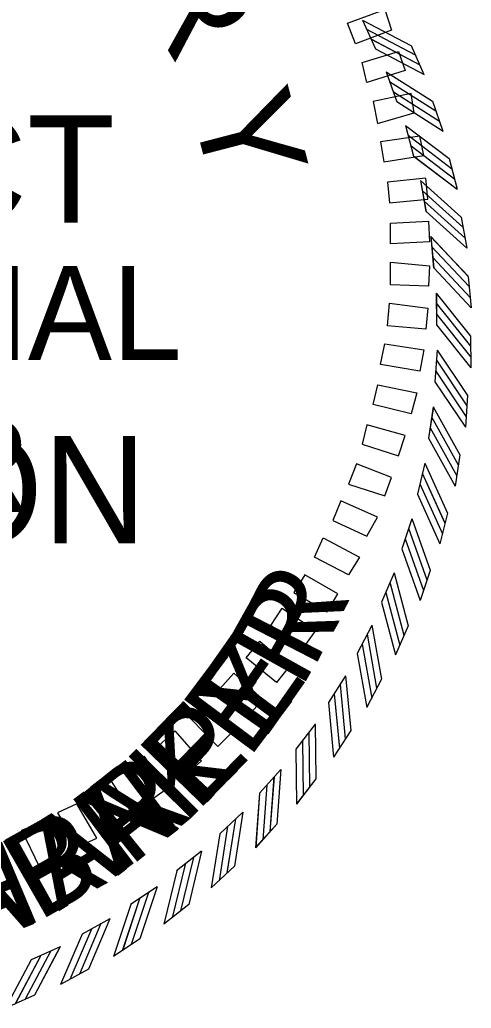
# Model space of a CAD drawing. Extents: x 16 to 1228740, y 11 to 152440.
# Drawn here: x 17.7977 to 17.8514, y 10.8205 to 10.9382 of the extents above; entities that cross this region are included whole.
import ezdxf

# ---------------------------------------------------------------- set-up
doc = ezdxf.new("R2010")
doc.units = 0
for name, color, linetype in [('B_StampERBB', 7, 'Continuous'), ('STAMP_FRED', 7, 'Continuous'), ('STAMP_JUSTIN', 7, 'Continuous'), ('STAMP_PRELIM', 7, 'Continuous')]:
    doc.layers.add(name, color=color, linetype=linetype)

msp = doc.modelspace()

# ---------------------------------------------------------------- linework, layer by layer
at = {"layer": 'B_StampERBB'}
for p, q in [((17.8385, 10.93817), (17.84005, 10.93472)), ((17.84427, 10.93512), (17.84581, 10.93169)), ((17.84132, 10.932), (17.84258, 10.92844)), ((17.84682, 10.92849), (17.84807, 10.92494)), ((17.84362, 10.92562), (17.84458, 10.92197)), ((17.84881, 10.92167), (17.84977, 10.91802)), ((17.84539, 10.91908), (17.84605, 10.91535)), ((17.85023, 10.91471), (17.85089, 10.91099)), ((17.84661, 10.9124), (17.84696, 10.90864)), ((17.85108, 10.90765), (17.85142, 10.9039)), ((17.84728, 10.90566), (17.84731, 10.90188)), ((17.85133, 10.90055), (17.85137, 10.89678)), ((17.84738, 10.89887), (17.8471, 10.89511)), ((17.851, 10.89345), (17.85073, 10.88969)), ((17.84693, 10.89211), (17.84634, 10.88837)), ((17.85009, 10.8864), (17.8495, 10.88268)), ((17.84591, 10.8854), (17.84502, 10.88173)), ((17.8486, 10.87945), (17.8477, 10.87579)), ((17.84435, 10.8788), (17.84316, 10.87522)), ((17.84225, 10.87235), (17.84076, 10.86888)), ((17.84653, 10.87265), (17.84534, 10.86908)), ((17.83962, 10.8661), (17.83786, 10.86276)), ((17.84392, 10.86605), (17.84243, 10.86258)), ((17.83649, 10.86009), (17.83445, 10.85691)), ((17.84076, 10.85968), (17.839, 10.85635)), ((17.83287, 10.85435), (17.83058, 10.85135)), ((17.83709, 10.85359), (17.83506, 10.85042)), ((17.82879, 10.84894), (17.82625, 10.84613)), ((17.83293, 10.84783), (17.83065, 10.84483)), ((17.82427, 10.84388), (17.82152, 10.84129)), ((17.82831, 10.84243), (17.82579, 10.83963)), ((17.81935, 10.83921), (17.81639, 10.83686)), ((17.82326, 10.83743), (17.82051, 10.83485)), ((17.81407, 10.83496), (17.81092, 10.83286)), ((17.81782, 10.83287), (17.81486, 10.83052)), ((17.80845, 10.83116), (17.80514, 10.82933)), ((17.81201, 10.82877), (17.80888, 10.82667)), ((17.80254, 10.82784), (17.79909, 10.82629)), ((17.80589, 10.82516), (17.80259, 10.82333)), ((17.79949, 10.82207), (17.79605, 10.82052))]:
    msp.add_line(p, q, dxfattribs=at)
for points in [[(17.83849, 10.93817), (17.84426, 10.93513)], [(17.83898, 10.93706), (17.84475, 10.93402)], [(17.83955, 10.93588), (17.84531, 10.93283)], [(17.84005, 10.93473), (17.84582, 10.93168)], [(17.84132, 10.93201), (17.84681, 10.92849)], [(17.84171, 10.93086), (17.84721, 10.92735)], [(17.84217, 10.92963), (17.84767, 10.92612)], [(17.84258, 10.92845), (17.84808, 10.92493)], [(17.84362, 10.92563), (17.84881, 10.92167)], [(17.84392, 10.92445), (17.8491, 10.9205)], [(17.84428, 10.92319), (17.84947, 10.91924)], [(17.84459, 10.92197), (17.84977, 10.91802)], [(17.84539, 10.91908), (17.85023, 10.91471)], [(17.84558, 10.91788), (17.85043, 10.91351)], [(17.84584, 10.9166), (17.85068, 10.91223)], [(17.84605, 10.91536), (17.85089, 10.91099)], [(17.84661, 10.91241), (17.85107, 10.90765)], [(17.84671, 10.9112), (17.85117, 10.90645)], [(17.84686, 10.9099), (17.85132, 10.90514)], [(17.84696, 10.90865), (17.85143, 10.90389)], [(17.84727, 10.90566), (17.85133, 10.90055)], [(17.84727, 10.90445), (17.85133, 10.89934)], [(17.84731, 10.90314), (17.85137, 10.89803)], [(17.84731, 10.90188), (17.85137, 10.89677)], [(17.84738, 10.89888), (17.851, 10.89345)], [(17.84728, 10.89767), (17.8509, 10.89225)], [(17.84721, 10.89636), (17.85083, 10.89094)], [(17.84711, 10.89511), (17.85073, 10.88969)], [(17.84692, 10.89211), (17.85009, 10.88641)], [(17.84672, 10.89092), (17.84989, 10.88521)], [(17.84655, 10.88962), (17.84971, 10.88391)], [(17.84634, 10.88838), (17.84951, 10.88267)], [(17.84591, 10.88541), (17.84859, 10.87946)], [(17.84561, 10.88423), (17.8483, 10.87828)], [(17.84533, 10.88295), (17.84801, 10.877)], [(17.84502, 10.88173), (17.84771, 10.87579)], [(17.84435, 10.87881), (17.84653, 10.87266)], [(17.84396, 10.87766), (17.84614, 10.87151)], [(17.84357, 10.87641), (17.84575, 10.87026)], [(17.84316, 10.87522), (17.84534, 10.86907)], [(17.84225, 10.87236), (17.84391, 10.86605)], [(17.84176, 10.87125), (17.84343, 10.86494)], [(17.84127, 10.87003), (17.84294, 10.86373)], [(17.84077, 10.86888), (17.84243, 10.86258)], [(17.83962, 10.86611), (17.84076, 10.85968)], [(17.83904, 10.86504), (17.84018, 10.85862)], [(17.83846, 10.86387), (17.8396, 10.85745)], [(17.83786, 10.86276), (17.839, 10.85634)], [(17.83649, 10.86009), (17.83709, 10.8536)], [(17.83582, 10.85908), (17.83643, 10.85258)], [(17.83514, 10.85796), (17.83575, 10.85146)], [(17.83446, 10.85691), (17.83506, 10.85041)], [(17.83287, 10.85436), (17.83293, 10.84784)], [(17.83135, 10.85234), (17.83142, 10.84582)], [(17.83212, 10.8534), (17.83219, 10.84688)], [(17.83058, 10.85135), (17.83065, 10.84483)], [(17.82879, 10.84894), (17.82831, 10.84244)], [(17.82797, 10.84805), (17.82749, 10.84154)], [(17.82711, 10.84706), (17.82664, 10.84055)], [(17.82626, 10.84613), (17.82579, 10.83963)], [(17.82338, 10.84306), (17.82237, 10.83661)], [(17.82427, 10.84388), (17.82326, 10.83744)], [(17.82244, 10.84214), (17.82144, 10.8357)], [(17.82152, 10.84129), (17.82051, 10.83485)], [(17.8184, 10.83847), (17.81686, 10.83213)], [(17.81936, 10.83921), (17.81782, 10.83287)], [(17.81739, 10.83763), (17.81585, 10.83129)], [(17.8164, 10.83686), (17.81486, 10.83052)], [(17.81407, 10.83496), (17.81202, 10.82877)], [(17.81198, 10.83355), (17.80993, 10.82736)], [(17.81305, 10.8343), (17.811, 10.82811)], [(17.81093, 10.83286), (17.80887, 10.82667)], [(17.80845, 10.83116), (17.80589, 10.82516)], [(17.80625, 10.82993), (17.80369, 10.82393)], [(17.80738, 10.83059), (17.80483, 10.82459)], [(17.80515, 10.82933), (17.80259, 10.82333)], [(17.80254, 10.82784), (17.79949, 10.82208)], [(17.80024, 10.82679), (17.7972, 10.82102)], [(17.80143, 10.82736), (17.79838, 10.82159)], [(17.79909, 10.82629), (17.79605, 10.82052)]]:
    msp.add_lwpolyline(points, dxfattribs=at)
at = {"layer": 'STAMP_FRED'}
for p, q in [((17.8385, 10.93817), (17.84005, 10.93472)), ((17.84427, 10.93512), (17.84581, 10.93169)), ((17.84132, 10.932), (17.84258, 10.92844)), ((17.84682, 10.92849), (17.84807, 10.92494)), ((17.84362, 10.92562), (17.84458, 10.92197)), ((17.84881, 10.92167), (17.84977, 10.91802)), ((17.84539, 10.91908), (17.84605, 10.91535)), ((17.85023, 10.91471), (17.85089, 10.91099)), ((17.84661, 10.9124), (17.84696, 10.90864)), ((17.85108, 10.90765), (17.85142, 10.9039)), ((17.84728, 10.90566), (17.84731, 10.90188)), ((17.85133, 10.90055), (17.85137, 10.89678)), ((17.84738, 10.89887), (17.8471, 10.89511)), ((17.851, 10.89345), (17.85073, 10.88969)), ((17.84693, 10.89211), (17.84634, 10.88837)), ((17.85009, 10.8864), (17.8495, 10.88268)), ((17.84591, 10.8854), (17.84502, 10.88173)), ((17.8486, 10.87945), (17.8477, 10.87579)), ((17.84435, 10.8788), (17.84316, 10.87522)), ((17.84225, 10.87235), (17.84076, 10.86888)), ((17.84653, 10.87265), (17.84534, 10.86908)), ((17.83962, 10.8661), (17.83786, 10.86276)), ((17.84392, 10.86605), (17.84243, 10.86258)), ((17.83649, 10.86009), (17.83445, 10.85691)), ((17.84076, 10.85968), (17.839, 10.85635)), ((17.83287, 10.85435), (17.83058, 10.85135)), ((17.83709, 10.85359), (17.83506, 10.85042)), ((17.82879, 10.84894), (17.82625, 10.84613)), ((17.83293, 10.84783), (17.83065, 10.84483)), ((17.82427, 10.84388), (17.82152, 10.84129)), ((17.82831, 10.84243), (17.82579, 10.83963)), ((17.81935, 10.83921), (17.81639, 10.83686)), ((17.82326, 10.83743), (17.82051, 10.83485)), ((17.81407, 10.83496), (17.81092, 10.83286)), ((17.81782, 10.83287), (17.81486, 10.83052)), ((17.80845, 10.83116), (17.80514, 10.82933)), ((17.81201, 10.82877), (17.80888, 10.82667)), ((17.80254, 10.82784), (17.79909, 10.82629)), ((17.80589, 10.82516), (17.80259, 10.82333)), ((17.79949, 10.82207), (17.79605, 10.82052))]:
    msp.add_line(p, q, dxfattribs=at)
for points in [[(17.83849, 10.93817), (17.84426, 10.93513)], [(17.83898, 10.93706), (17.84475, 10.93402)], [(17.83955, 10.93588), (17.84531, 10.93283)], [(17.84005, 10.93473), (17.84582, 10.93168)], [(17.84132, 10.93201), (17.84681, 10.92849)], [(17.84171, 10.93086), (17.84721, 10.92735)], [(17.84217, 10.92963), (17.84767, 10.92612)], [(17.84258, 10.92845), (17.84808, 10.92493)], [(17.84362, 10.92563), (17.84881, 10.92167)], [(17.84392, 10.92445), (17.8491, 10.9205)], [(17.84428, 10.92319), (17.84947, 10.91924)], [(17.84459, 10.92197), (17.84977, 10.91802)], [(17.84539, 10.91908), (17.85023, 10.91471)], [(17.84558, 10.91788), (17.85043, 10.91351)], [(17.84584, 10.9166), (17.85068, 10.91223)], [(17.84605, 10.91536), (17.85089, 10.91099)], [(17.84661, 10.91241), (17.85107, 10.90765)], [(17.84671, 10.9112), (17.85117, 10.90645)], [(17.84686, 10.9099), (17.85132, 10.90514)], [(17.84696, 10.90865), (17.85143, 10.90389)], [(17.84727, 10.90566), (17.85133, 10.90055)], [(17.84727, 10.90445), (17.85133, 10.89934)], [(17.84731, 10.90314), (17.85137, 10.89803)], [(17.84731, 10.90188), (17.85137, 10.89677)], [(17.84738, 10.89888), (17.851, 10.89345)], [(17.84728, 10.89767), (17.8509, 10.89225)], [(17.84721, 10.89636), (17.85083, 10.89094)], [(17.84711, 10.89511), (17.85073, 10.88969)], [(17.84692, 10.89211), (17.85009, 10.88641)], [(17.84672, 10.89092), (17.84989, 10.88521)], [(17.84655, 10.88962), (17.84971, 10.88391)], [(17.84634, 10.88838), (17.84951, 10.88267)], [(17.84591, 10.88541), (17.84859, 10.87946)], [(17.84561, 10.88423), (17.8483, 10.87828)], [(17.84533, 10.88295), (17.84801, 10.877)], [(17.84502, 10.88173), (17.84771, 10.87579)], [(17.84435, 10.87881), (17.84653, 10.87266)], [(17.84396, 10.87766), (17.84614, 10.87151)], [(17.84357, 10.87641), (17.84575, 10.87026)], [(17.84316, 10.87522), (17.84534, 10.86907)], [(17.84225, 10.87236), (17.84391, 10.86605)], [(17.84176, 10.87125), (17.84343, 10.86494)], [(17.84127, 10.87003), (17.84294, 10.86373)], [(17.84077, 10.86888), (17.84243, 10.86258)], [(17.83962, 10.86611), (17.84076, 10.85968)], [(17.83904, 10.86504), (17.84018, 10.85862)], [(17.83846, 10.86387), (17.8396, 10.85745)], [(17.83786, 10.86276), (17.839, 10.85634)], [(17.83649, 10.86009), (17.83709, 10.8536)], [(17.83582, 10.85908), (17.83643, 10.85258)], [(17.83514, 10.85796), (17.83575, 10.85146)], [(17.83446, 10.85691), (17.83506, 10.85041)], [(17.83287, 10.85436), (17.83293, 10.84784)], [(17.83135, 10.85234), (17.83142, 10.84582)], [(17.83212, 10.8534), (17.83219, 10.84688)], [(17.83058, 10.85135), (17.83065, 10.84483)], [(17.82879, 10.84894), (17.82831, 10.84244)], [(17.82797, 10.84805), (17.82749, 10.84154)], [(17.82711, 10.84706), (17.82664, 10.84055)], [(17.82626, 10.84613), (17.82579, 10.83963)], [(17.82338, 10.84306), (17.82237, 10.83661)], [(17.82427, 10.84388), (17.82326, 10.83744)], [(17.82244, 10.84214), (17.82144, 10.8357)], [(17.82152, 10.84129), (17.82051, 10.83485)], [(17.8184, 10.83847), (17.81686, 10.83213)], [(17.81936, 10.83921), (17.81782, 10.83287)], [(17.81739, 10.83763), (17.81585, 10.83129)], [(17.8164, 10.83686), (17.81486, 10.83052)], [(17.81407, 10.83496), (17.81202, 10.82877)], [(17.81198, 10.83355), (17.80993, 10.82736)], [(17.81305, 10.8343), (17.811, 10.82811)], [(17.81093, 10.83286), (17.80887, 10.82667)], [(17.80845, 10.83116), (17.80589, 10.82516)], [(17.80625, 10.82993), (17.80369, 10.82393)], [(17.80738, 10.83059), (17.80483, 10.82459)], [(17.80515, 10.82933), (17.80259, 10.82333)], [(17.80254, 10.82784), (17.79949, 10.82208)], [(17.80024, 10.82679), (17.7972, 10.82102)], [(17.80143, 10.82736), (17.79838, 10.82159)], [(17.79909, 10.82629), (17.79605, 10.82052)]]:
    msp.add_lwpolyline(points, dxfattribs=at)
at = {"layer": 'STAMP_JUSTIN'}
for p, q in [((17.8385, 10.93817), (17.84005, 10.93472)), ((17.84427, 10.93512), (17.84581, 10.93169)), ((17.84132, 10.932), (17.84258, 10.92844)), ((17.84682, 10.92849), (17.84807, 10.92494)), ((17.84362, 10.92562), (17.84458, 10.92197)), ((17.84881, 10.92167), (17.84977, 10.91802)), ((17.84539, 10.91908), (17.84604, 10.91536)), ((17.85023, 10.91471), (17.85089, 10.91099)), ((17.84661, 10.91241), (17.84695, 10.90864)), ((17.85107, 10.90765), (17.85142, 10.9039)), ((17.84727, 10.90566), (17.84731, 10.90188)), ((17.85133, 10.90055), (17.85137, 10.89678)), ((17.84738, 10.89888), (17.8471, 10.89511)), ((17.851, 10.89345), (17.85073, 10.88969)), ((17.84692, 10.89211), (17.84634, 10.88838)), ((17.85009, 10.8864), (17.8495, 10.88268)), ((17.84591, 10.8854), (17.84502, 10.88173)), ((17.84859, 10.87946), (17.8477, 10.87579)), ((17.84435, 10.8788), (17.84316, 10.87522)), ((17.84225, 10.87236), (17.84076, 10.86888)), ((17.84653, 10.87265), (17.84534, 10.86908)), ((17.83962, 10.8661), (17.83785, 10.86276)), ((17.84391, 10.86605), (17.84243, 10.86258)), ((17.83649, 10.86009), (17.83445, 10.85691)), ((17.84076, 10.85968), (17.839, 10.85635)), ((17.83287, 10.85435), (17.83057, 10.85135)), ((17.83709, 10.85359), (17.83506, 10.85042)), ((17.82879, 10.84894), (17.82625, 10.84614)), ((17.83293, 10.84783), (17.83064, 10.84484)), ((17.82427, 10.84388), (17.82151, 10.84129)), ((17.82831, 10.84243), (17.82578, 10.83964)), ((17.81935, 10.83921), (17.81639, 10.83686)), ((17.82326, 10.83743), (17.82051, 10.83485)), ((17.81407, 10.83496), (17.81092, 10.83286)), ((17.81782, 10.83287), (17.81486, 10.83053)), ((17.80845, 10.83116), (17.80514, 10.82933)), ((17.81201, 10.82877), (17.80887, 10.82668)), ((17.80253, 10.82784), (17.79909, 10.82629)), ((17.80589, 10.82516), (17.80259, 10.82334)), ((17.79949, 10.82207), (17.79605, 10.82053))]:
    msp.add_line(p, q, dxfattribs=at)
for points in [[(17.83849, 10.93817), (17.84426, 10.93513)], [(17.83898, 10.93706), (17.84475, 10.93402)], [(17.83954, 10.93588), (17.84531, 10.93283)], [(17.84005, 10.93473), (17.84582, 10.93168)], [(17.84131, 10.93201), (17.84681, 10.92849)], [(17.84171, 10.93086), (17.8472, 10.92735)], [(17.84217, 10.92963), (17.84767, 10.92612)], [(17.84258, 10.92845), (17.84808, 10.92493)], [(17.84362, 10.92563), (17.8488, 10.92167)], [(17.84391, 10.92445), (17.8491, 10.9205)], [(17.84427, 10.92319), (17.84946, 10.91924)], [(17.84458, 10.92197), (17.84977, 10.91802)], [(17.84538, 10.91908), (17.85023, 10.91471)], [(17.84558, 10.91788), (17.85043, 10.91351)], [(17.84584, 10.9166), (17.85068, 10.91223)], [(17.84605, 10.91536), (17.85089, 10.91099)], [(17.8466, 10.91241), (17.85107, 10.90766)], [(17.8467, 10.9112), (17.85117, 10.90645)], [(17.84685, 10.9099), (17.85132, 10.90515)], [(17.84696, 10.90865), (17.85142, 10.90389)], [(17.84727, 10.90566), (17.85133, 10.90055)], [(17.84727, 10.90445), (17.85133, 10.89934)], [(17.84731, 10.90314), (17.85137, 10.89803)], [(17.84731, 10.90188), (17.85137, 10.89678)], [(17.84738, 10.89888), (17.851, 10.89346)], [(17.84728, 10.89767), (17.8509, 10.89225)], [(17.84721, 10.89636), (17.85083, 10.89094)], [(17.8471, 10.89511), (17.85073, 10.88969)], [(17.84692, 10.89211), (17.85008, 10.88641)], [(17.84672, 10.89092), (17.84988, 10.88521)], [(17.84655, 10.88962), (17.84971, 10.88391)], [(17.84634, 10.88838), (17.8495, 10.88268)], [(17.84591, 10.88541), (17.84859, 10.87946)], [(17.84561, 10.88423), (17.84829, 10.87829)], [(17.84533, 10.88295), (17.84801, 10.87701)], [(17.84502, 10.88174), (17.8477, 10.87579)], [(17.84435, 10.87881), (17.84653, 10.87266)], [(17.84395, 10.87766), (17.84614, 10.87151)], [(17.84357, 10.87641), (17.84575, 10.87026)], [(17.84316, 10.87522), (17.84534, 10.86907)], [(17.84225, 10.87236), (17.84391, 10.86605)], [(17.84176, 10.87125), (17.84343, 10.86494)], [(17.84127, 10.87003), (17.84294, 10.86373)], [(17.84077, 10.86888), (17.84243, 10.86258)], [(17.83962, 10.86611), (17.84076, 10.85969)], [(17.83904, 10.86504), (17.84018, 10.85862)], [(17.83846, 10.86387), (17.8396, 10.85745)], [(17.83786, 10.86277), (17.839, 10.85634)], [(17.83649, 10.8601), (17.83709, 10.8536)], [(17.83582, 10.85908), (17.83643, 10.85258)], [(17.83514, 10.85796), (17.83575, 10.85147)], [(17.83445, 10.85691), (17.83506, 10.85041)], [(17.83287, 10.85436), (17.83293, 10.84784)], [(17.83135, 10.85234), (17.83142, 10.84582)], [(17.83212, 10.8534), (17.83219, 10.84688)], [(17.83058, 10.85135), (17.83064, 10.84483)], [(17.82879, 10.84894), (17.82831, 10.84244)], [(17.82796, 10.84805), (17.82749, 10.84155)], [(17.82711, 10.84706), (17.82663, 10.84055)], [(17.82626, 10.84614), (17.82578, 10.83963)], [(17.82338, 10.84306), (17.82237, 10.83662)], [(17.82427, 10.84388), (17.82326, 10.83744)], [(17.82244, 10.84215), (17.82144, 10.8357)], [(17.82152, 10.84129), (17.82051, 10.83485)], [(17.8184, 10.83847), (17.81686, 10.83213)], [(17.81935, 10.83921), (17.81782, 10.83287)], [(17.81739, 10.83763), (17.81585, 10.83129)], [(17.8164, 10.83686), (17.81486, 10.83052)], [(17.81407, 10.83496), (17.81201, 10.82877)], [(17.81198, 10.83355), (17.80992, 10.82736)], [(17.81305, 10.8343), (17.811, 10.82811)], [(17.81093, 10.83286), (17.80887, 10.82667)], [(17.80845, 10.83117), (17.80589, 10.82517)], [(17.80625, 10.82993), (17.80369, 10.82393)], [(17.80738, 10.83059), (17.80482, 10.82459)], [(17.80515, 10.82933), (17.80259, 10.82333)], [(17.80254, 10.82785), (17.79949, 10.82208)], [(17.80024, 10.8268), (17.7972, 10.82103)], [(17.80143, 10.82736), (17.79838, 10.82159)], [(17.79909, 10.82629), (17.79605, 10.82052)]]:
    msp.add_lwpolyline(points, dxfattribs=at)
at = {"layer": 'STAMP_PRELIM'}
for p, q in [((17.83671, 10.93778), (17.84115, 10.93941)), ((17.84115, 10.93941), (17.84196, 10.93697)), ((17.83765, 10.93535), (17.83671, 10.93778)), ((17.84196, 10.93697), (17.83765, 10.93535)), ((17.83846, 10.9331), (17.84278, 10.93441)), ((17.84278, 10.93441), (17.84358, 10.93216)), ((17.83903, 10.93072), (17.83846, 10.9331)), ((17.84358, 10.93216), (17.83903, 10.93072)), ((17.84428, 10.92941), (17.83978, 10.92847)), ((17.84465, 10.9271), (17.84428, 10.92941)), ((17.83978, 10.92847), (17.84028, 10.92585)), ((17.84028, 10.92585), (17.84465, 10.9271)), ((17.84533, 10.92435), (17.84065, 10.92366)), ((17.84578, 10.92203), (17.84533, 10.92435)), ((17.84065, 10.92366), (17.84103, 10.92128)), ((17.84103, 10.92128), (17.84578, 10.92203)), ((17.84603, 10.91935), (17.84146, 10.91885)), ((17.84628, 10.91685), (17.84603, 10.91935)), ((17.84146, 10.91885), (17.84171, 10.91641)), ((17.84171, 10.91641), (17.84628, 10.91685)), ((17.84183, 10.91397), (17.84633, 10.91422)), ((17.84183, 10.91153), (17.84183, 10.91397)), ((17.84633, 10.91422), (17.84646, 10.91178)), ((17.84646, 10.91178), (17.84183, 10.91153)), ((17.84183, 10.90935), (17.84646, 10.90891)), ((17.84183, 10.90666), (17.84183, 10.90935)), ((17.84646, 10.90891), (17.84633, 10.90647)), ((17.84633, 10.90647), (17.84183, 10.90666)), ((17.84146, 10.90178), (17.84171, 10.90447)), ((17.84171, 10.90447), (17.84628, 10.90385)), ((17.84628, 10.90385), (17.84603, 10.90135)), ((17.84603, 10.90135), (17.84146, 10.90178)), ((17.84065, 10.89716), (17.84115, 10.8996)), ((17.84115, 10.8996), (17.84578, 10.89891)), ((17.84578, 10.89891), (17.84533, 10.89635)), ((17.84533, 10.89635), (17.84065, 10.89716)), ((17.83978, 10.89241), (17.84033, 10.89472)), ((17.84033, 10.89472), (17.84496, 10.89378)), ((17.84496, 10.89378), (17.84428, 10.89128)), ((17.84428, 10.89128), (17.83978, 10.89241)), ((17.83903, 10.88997), (17.83846, 10.88766)), ((17.84358, 10.88872), (17.83903, 10.88997)), ((17.84278, 10.88628), (17.84358, 10.88872)), ((17.83846, 10.88766), (17.84278, 10.88628)), ((17.83778, 10.88535), (17.83683, 10.88291)), ((17.84196, 10.88372), (17.83778, 10.88535)), ((17.83683, 10.88291), (17.84115, 10.88153)), ((17.84115, 10.88153), (17.84196, 10.88372)), ((17.8359, 10.88091), (17.83496, 10.8786)), ((17.84028, 10.87897), (17.8359, 10.88091)), ((17.83496, 10.8786), (17.83903, 10.87672)), ((17.83903, 10.87672), (17.84028, 10.87897)), ((17.83278, 10.87422), (17.83383, 10.87653)), ((17.83383, 10.87653), (17.83815, 10.87422)), ((17.83683, 10.8721), (17.83278, 10.87422)), ((17.83815, 10.87422), (17.83683, 10.8721)), ((17.83165, 10.8721), (17.83033, 10.87003)), ((17.83558, 10.86985), (17.83165, 10.8721)), ((17.83033, 10.87003), (17.83428, 10.86772)), ((17.83428, 10.86772), (17.83558, 10.86985)), ((17.82758, 10.8661), (17.82896, 10.86816)), ((17.82896, 10.86816), (17.8329, 10.86547)), ((17.83133, 10.86328), (17.82758, 10.8661)), ((17.8329, 10.86547), (17.83133, 10.86328)), ((17.82465, 10.86222), (17.82628, 10.86422)), ((17.82628, 10.86422), (17.82978, 10.86122)), ((17.82828, 10.85928), (17.82465, 10.86222)), ((17.82978, 10.86122), (17.82828, 10.85928)), ((17.82321, 10.86041), (17.82153, 10.85853)), ((17.82665, 10.85728), (17.82321, 10.86041)), ((17.82153, 10.85853), (17.8249, 10.85535)), ((17.8249, 10.85535), (17.82665, 10.85728)), ((17.81978, 10.85685), (17.81803, 10.85503)), ((17.82315, 10.85353), (17.81978, 10.85685)), ((17.81803, 10.85503), (17.82128, 10.85166)), ((17.81621, 10.85353), (17.81428, 10.85178)), ((17.81933, 10.84997), (17.81621, 10.85353)), ((17.82128, 10.85166), (17.82315, 10.85353)), ((17.81428, 10.85178), (17.81753, 10.84835)), ((17.81258, 10.85047), (17.81053, 10.84891)), ((17.81515, 10.8466), (17.81258, 10.85047)), ((17.81753, 10.84835), (17.81933, 10.84997)), ((17.81053, 10.84891), (17.81328, 10.84528)), ((17.80858, 10.84766), (17.80646, 10.84622)), ((17.81115, 10.84366), (17.80858, 10.84766)), ((17.81328, 10.84528), (17.81515, 10.8466)), ((17.80646, 10.84622), (17.80908, 10.84235)), ((17.80453, 10.84485), (17.80221, 10.84378)), ((17.8069, 10.84078), (17.80453, 10.84485)), ((17.80221, 10.84378), (17.80465, 10.83972)), ((17.80908, 10.84235), (17.81115, 10.84366)), ((17.79796, 10.84172), (17.80028, 10.84266)), ((17.80008, 10.83735), (17.79796, 10.84172)), ((17.80028, 10.84266), (17.80221, 10.8386)), ((17.80465, 10.83972), (17.8069, 10.84078)), ((17.80221, 10.8386), (17.80008, 10.83735))]:
    msp.add_line(p, q, dxfattribs=at)

# ---------------------------------------------------------------- texts
at = {"layer": 'B_StampERBB'}
for s, height, p in [('PROFESSIONAL', 0.0111938, (17.70056, 10.89771)), ('ENGINEER', 0.011194, (17.72082, 10.87959))]:
    msp.add_text(s, height=height, dxfattribs=at).set_placement(p)
for s, rotation, p in [('R', 60.8178, (17.8312, 10.85844)), ('E', 53.157, (17.82494, 10.85009)), ('K', 45.1314, (17.81726, 10.84232)), ('A', 37.8354, (17.80939, 10.83625)), ('B', 29.8098, (17.79993, 10.83079))]:
    msp.add_text(s, height=0.01042, rotation=rotation, dxfattribs=at).set_placement(p)
at = {"layer": 'STAMP_FRED'}
for s, height, p in [('PROFESSIONAL', 0.0111938, (17.70056, 10.89771)), ('ENGINEER', 0.011194, (17.72082, 10.87959))]:
    msp.add_text(s, height=height, dxfattribs=at).set_placement(p)
for s, rotation, p in [('R', 62.6418, (17.83263, 10.86077)), ('E', 54.981, (17.82667, 10.85221)), ('P', 46.9554, (17.81927, 10.84417)), ('R', 38.9298, (17.81081, 10.83725)), ('A', 31.6338, (17.80236, 10.83204)), ('H', 22.8786, (17.79144, 10.82727))]:
    msp.add_text(s, height=0.01042, rotation=rotation, dxfattribs=at).set_placement(p)
at = {"layer": 'STAMP_JUSTIN'}
for s, height, p in [('PROFESSIONAL', 0.0111936, (17.70056, 10.89771)), ('ENGINEER', 0.011194, (17.72082, 10.87959))]:
    msp.add_text(s, height=height, dxfattribs=at).set_placement(p)
for s, rotation, p in [('Y', 53.4433, (17.82593, 10.85139)), ('E', 45.7825, (17.81878, 10.8438)), ('N', 37.0272, (17.80946, 10.83639)), ('R', 29.0016, (17.80002, 10.83092)), ('A', 21.7056, (17.79084, 10.82713))]:
    msp.add_text(s, height=0.01042, rotation=rotation, dxfattribs=at).set_placement(p)
at = {"layer": 'STAMP_PRELIM'}
for s, rotation, p in [('R', 301.0067, (17.81071, 10.94228)), ('Y', 284.5896, (17.81803, 10.92797))]:
    msp.add_text(s, height=0.01184, rotation=rotation, dxfattribs=at).set_placement(p)
for s, p in [('SUBJECT', (17.73109, 10.91403)), ('REVISION', (17.73109, 10.87585))]:
    msp.add_text(s, height=0.012794, dxfattribs=at).set_placement(p)

doc.saveas('drawing.dxf')
